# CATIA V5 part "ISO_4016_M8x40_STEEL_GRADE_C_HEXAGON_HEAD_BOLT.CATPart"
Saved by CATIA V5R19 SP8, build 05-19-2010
Part number: ISO 4016 BOLT M8x40 STEEL GRADE C HEXAGON HEAD
Nomenclature: 27
Publications: "Mating Face", "Axis"
Bounding box of the stored display mesh (mm): x -40 to 6.275, y -6.5 to 6.5, z -7.506 to 7.506
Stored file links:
  C:\Users\rphgr\Desktop\0_Tapis_TC520B_vitesse\ISO_4016_M8x40_STEEL_GRADE_C_HEXAGON_HEAD_BOLT.CATPart
  D:\Programmes\DassaultSysteme\win_b64\startup\components\MechanicalStandardParts\EN_Standards\Design_Tables\EN_ISO_4016_GRADE_C_HEXAGON_HEAD_BOLT.txt
  C:\Program Files\Dassault Systemes\B19\win_b64\startup\components\MechanicalStandardParts\ISO_Standards\Design_Tables\ISO_4016_GRADE_C_HEXAGON_HEAD_BOLT.txt
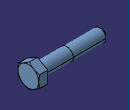
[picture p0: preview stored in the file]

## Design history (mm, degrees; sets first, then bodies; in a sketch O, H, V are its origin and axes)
Parameters
  d_dia = 8 mm
  l_length = 40 mm
  k_max_head_depth = 5.675 mm
  r_min = 0.4 mm
  s_nom_across_flats = 13 mm
  c_max = 0.6 mm
  dw_min = 11.47 mm
  p_pitch = 1.25 mm
  threading = 22 mm
Body1 "PartBody" (main body)
  Sketch1 on yz-plane, origin (0, 0, 0), H (0, 1, 0), V (0, 0, 1)
    circle A1 centre (0, 0) radius 5.735
    radius A1 = 5.735 {= dw_min /2}
  Pad1: profile Sketch1, direction (1, 0, 0), length 0.6 {= c_max}
  Sketch2 on face of Pad1, origin (0.6, 0, 0), H (0, 1, 0), V (0, 0, 1)
    point P1 (6.5, -3.7528)
    point P2 (6.5, 3.7528)
    point P3 (0, 7.5056)
    point P4 (-6.5, 3.7528)
    point P5 (-6.5, -3.7528)
    point P6 (0, -7.5056)
    point P7 (6.5, 0)
    line L1 (6.5, -3.7528) -> (6.5, 3.7528)
    line L2 (6.5, 3.7528) -> (0, 7.5056)
    line L3 (0, 7.5056) -> (-6.5, 3.7528)
    line L4 (-6.5, 3.7528) -> (-6.5, -3.7528)
    line L5 (-6.5, -3.7528) -> (0, -7.5056)
    line L6 (0, -7.5056) -> (6.5, -3.7528)
    construction line L7 (0, 0) -> (6.5, 0)
    construction circle A1 centre (0, 0) radius 7.5056
    construction arc A2 centre (-6.5, -3.7528) radius 7.5056 from (-6.5, 3.7528) to (0, -7.5056) cw
    construction arc A3 centre (6.5, 3.7528) radius 7.5056 from (0, 7.5056) to (6.5, -3.7528) ccw
    point P8 (-6.5, -3.7528)
    point P9 (6.5, 3.7528)
    distance L1 L4 = 13 {= s_nom_across_flats}
    horizontal: L7 H
    coincidence: A1 P1, A1 P2, A1 P3, A1 P4, A1 P5, A1 P6, A2 P4, A2 P6, A2 O, P8 P5, A3 P3, A3 P1, A3 O, P9 P2
    midpoint: P7 L1
  Pad2: profile Sketch2, direction (1, 0, 0), length 5.675 {= k_max_head_depth}
  Sketch3 on zx-plane, origin (0, 0, 0), H (-1, 0, 0), V (0, 0, 1)
    point P1 (-6.275, 6.4968)
    axis line L1 (-94.6904, 0) -> (76.7146, 0)
    reference intersected line E1 through (1000000, 0) direction (-1, 0) from xy-plane
    line L2 (-5.6926, 7.5056) -> (-6.275, 6.4968)
    line L3 (-5.6926, 7.5056) -> (-6.275, 7.5056)
    line L4 (-6.275, 7.5056) -> (-6.275, 6.4968)
    reference projected line E2 (-0.8, 7.5056) -> (-18.28, 7.5056) from edge [face of Pad2 | face of Pad2]
    distance P1 H = 6.4968 {= s_nom_across_flats /2.001}
    distance P1 V = 6.275 {= k_max_head_depth +c_max}
    angle L4 L2 = 30
    horizontal: L1 H, L3 H
    coincidence: L1 E1, L3 E2
    vertical: L4 V
  Groove1: profile Sketch3, axis Sketch3.L1, angle 360
  Sketch4 on face of Pad1, origin (0, 0, 0), H (0, -1, 0), V (0, 0, 1)
    circle A1 centre (0, 0) radius 4
    radius A1 = 4 {= d_dia /2}
  Pad3: profile Sketch4, direction (-1, 0, 0), length 18 {= l_length -threading}
  Sketch5 on face of Pad3, origin (-18, 0, 0), H (0, -1, 0), V (0, 0, 1)
    circle A1 centre (0, 0) radius 3.9024
    radius A1 = 3.9024 {= d_dia /2.05}
  Pad4: profile Sketch5, direction (-1, 0, 0), length 22 {= threading}
  Chamfer1: length 1.25 {= p_pitch}, angle 45, on face of Pad4
  Fillet1: radius 0.4 {= r_min}, on edge [face of Pad3 | face of Pad1]
  Thread1: diameter 7.8049 {= d_dia /1.025}, depth 22 {= threading}, pitch 1, on face of Pad4, from face of Pad4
